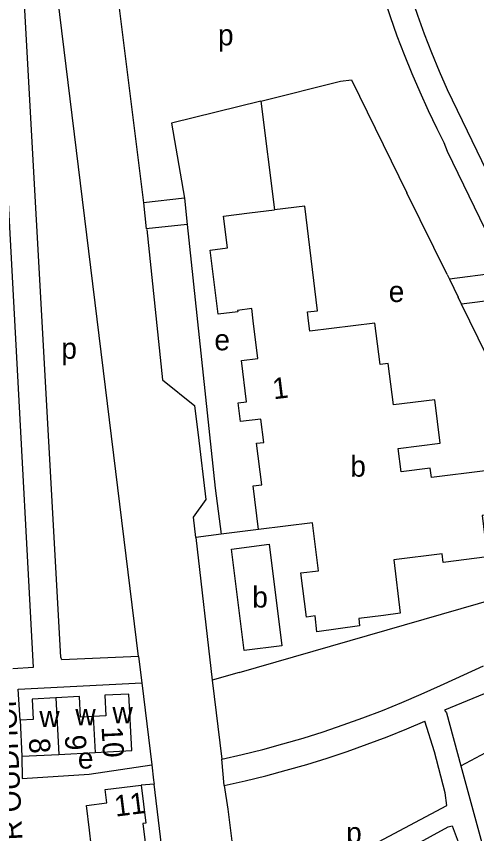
# Model space of a CAD drawing. Extents: x 157569 to 159501, y 382907 to 384670.
# Drawn here: x 158968.1 to 159055.8, y 383402.3 to 383558 of the extents above; entities that cross this region are included whole.
import ezdxf

# ---------------------------------------------------------------- set-up
doc = ezdxf.new("R2010")
doc.units = 0
for name, color, linetype in [('BLT_Basislijn', 7, 'Continuous'), ('BLT_Bebouwing', 7, 'Continuous'), ('BLT_Centroide', 7, 'Continuous'), ('BLT_Huisnummer', 7, 'Continuous'), ('BLT_Huisnummer_reeks', 7, 'Continuous'), ('BLT_Onderverdeling_panden', 7, 'Continuous'), ('BLT_Straatnaam_verkleind', 7, 'Continuous')]:
    doc.layers.add(name, color=color, linetype=linetype)

msp = doc.modelspace()

# ---------------------------------------------------------------- linework, layer by layer
at = {"layer": 'BLT_Basislijn'}
for p, q in [((158986.65, 383568.38), (158992.35, 383522.47)), ((158991.4, 383436.09), (158976.02, 383561.51)), ((159014.71, 383541.81), (158997.71, 383537.61)), ((159014.71, 383541.81), (159017.32, 383521.12)), ((158997.71, 383537.61), (159000.13, 383523.31)), ((159053.97, 383536.19), (159078.77, 383484.5)), ((159049.52, 383533.92), (159050.18, 383532.32)), ((159050.18, 383532.32), (159061.28, 383509.28)), ((159050.13, 383508.83), (159042.48, 383524.33)), ((159000.13, 383523.31), (158992.35, 383522.47)), ((158992.35, 383522.47), (158992.88, 383517.5)), ((159000.13, 383523.31), (159000.66, 383518.34)), ((159000.66, 383518.34), (158992.88, 383517.5)), ((159050.13, 383508.83), (159050.59, 383507.89)), ((159061.28, 383509.28), (159050.59, 383507.89)), ((159050.59, 383507.89), (159052.25, 383504.52)), ((159052.92, 383503.15), (159052.25, 383504.52)), ((159063.57, 383504.54), (159052.92, 383503.15)), ((159014.25, 383460.27), (159007.15, 383459.35)), ((159007.15, 383459.35), (159002.31, 383458.73)), ((159002.31, 383458.73), (159005.44, 383431.57)), ((158991.4, 383436.09), (158992.01, 383431.08)), ((159049.58, 383430.87), (159057.07, 383434.28)), ((159052.79, 383415.23), (159086.49, 383433.6)), ((159010.57, 383433.04), (159005.44, 383431.57)), ((158992.01, 383431.08), (158993.91, 383415.47)), ((159005.44, 383431.57), (159007.26, 383416.5)), ((159050.03, 383425.36), (159052.79, 383415.23)), ((159007.74, 383411.49), (159007.26, 383416.5)), ((158994.36, 383411.78), (158991.89, 383411.58))]:
    msp.add_line(p, q, dxfattribs=at)
for points in [[(159035.67, 383595.07), (159036.2, 383591.31), (159036.81, 383587.55), (159037.5, 383583.82), (159038.27, 383580.09), (159039.12, 383576.39), (159040.04, 383572.7), (159041.04, 383569.03), (159042.12, 383565.39), (159043.28, 383561.76), (159044.51, 383558.17), (159045.81, 383554.6), (159047.2, 383551.05), (159048.65, 383547.54), (159050.18, 383544.06), (159053.97, 383536.19)], [(159033.08, 383580.46), (159033.14, 383580.18), (159033.97, 383576.42), (159034.88, 383572.68), (159035.87, 383568.95), (159036.94, 383565.25), (159038.08, 383561.57), (159039.3, 383557.91), (159040.6, 383554.28), (159041.97, 383550.68), (159043.41, 383547.11), (159044.93, 383543.56), (159046.52, 383540.05), (159048.18, 383536.58), (159049.52, 383533.92)], [(158991.4, 383436.09), (158976.81, 383435.46), (158976.6, 383435.94), (158969.71, 383560.27)], [(158964.58, 383559.14), (158971.38, 383433.97), (158967.47, 383433.71)], [(159014.71, 383541.81), (159029.86, 383545.63), (159031.93, 383545.88), (159042.48, 383524.33)], [(159000.66, 383518.34), (159006.02, 383468.12)], [(158992.97, 383517.35), (158996, 383488.78), (159002.12, 383483.77)], [(159010.57, 383433.04), (159077.27, 383452.24), (159075.29, 383457.44), (159052.92, 383503.15)], [(159002.31, 383458.73), (159001.89, 383462.62), (159004.28, 383465.97), (159002.84, 383478.26), (159002.12, 383483.77)], [(159006.02, 383468.12), (159007.15, 383459.35)], [(158968.85, 383423.93), (158968.47, 383429.85), (158992.01, 383431.08)], [(159007.26, 383416.5), (159011.16, 383417.4), (159015.04, 383418.37), (159018.9, 383419.42), (159022.74, 383420.55), (159026.56, 383421.75), (159030.35, 383423.03), (159034.12, 383424.38), (159037.85, 383425.81), (159041.56, 383427.32), (159045.24, 383428.9), (159048.88, 383430.55), (159049.58, 383430.87)], [(159059.36, 383429.83), (159049.68, 383425.86), (159050.03, 383425.36)], [(159007.74, 383411.49), (159011.69, 383412.38), (159015.62, 383413.35), (159019.54, 383414.4), (159023.43, 383415.53), (159027.3, 383416.73), (159031.14, 383418.01), (159034.96, 383419.36), (159038.75, 383420.79), (159042.51, 383422.3), (159045.92, 383423.74)], [(159012.14, 383387.53), (159050.09, 383407.72), (159049.75, 383410.1), (159047.73, 383417.9), (159045.92, 383423.74)], [(158969.2, 383417.07), (158969.25, 383412.82), (158982.04, 383413.67), (158993.91, 383415.47)], [(158993.91, 383415.47), (158994.27, 383412.51), (158994.36, 383411.78)], [(159052.79, 383415.23), (159063.54, 383375.73), (159055.87, 383360.08), (159056.14, 383358.62), (159057.95, 383354.93)], [(158973.27, 383382.34), (158995.52, 383388.93), (158997.04, 383389.62), (158994.36, 383411.78)], [(159007.74, 383411.49), (159008.38, 383407.02), (159009.67, 383396.84), (159010.29, 383391.5), (159011.35, 383388.75), (159012.14, 383387.53)], [(159028.76, 383391.86), (159050.35, 383403.64), (159051.14, 383403.8), (159053, 383398.73), (159058.78, 383376.99), (159058.82, 383375.95), (159049, 383355.73)]]:
    msp.add_lwpolyline(points, dxfattribs=at)
at = {"layer": 'BLT_Bebouwing'}
for p, q in [((159023.06, 383521.82), (159017.32, 383521.12)), ((158969.2, 383417.07), (158976.22, 383417.43)), ((158976.22, 383417.43), (158983.13, 383417.79)), ((158992.23, 383404.25), (158992.74, 383400.13))]:
    msp.add_line(p, q, dxfattribs=at)
for points in [[(159007.58, 383519.92), (159012.53, 383520.53), (159017.32, 383521.12)], [(159048.85, 383476.68), (159047.83, 383484.94), (159039.92, 383483.97), (159038.94, 383491.89), (159037.39, 383491.7), (159036.42, 383499.56), (159024.02, 383498.03), (159023.76, 383500), (159023.55, 383501.68), (159025.5, 383501.92), (159023.06, 383521.82)], [(159014.25, 383460.27), (159013.23, 383468.56), (159014.86, 383468.76), (159013.89, 383476.67), (159015.27, 383476.84), (159014.72, 383481.28), (159010.81, 383480.79), (159010.37, 383484.34), (159011.99, 383484.54), (159011.01, 383492.45), (159014.14, 383492.83), (159013.25, 383500), (159012.96, 383502.31), (159010.27, 383501.98), (159010.31, 383501.69), (159006.55, 383501.23), (159005.05, 383513.46), (159008.32, 383513.86), (159007.58, 383519.92)], [(159057.37, 383471.41), (159047.15, 383470.15), (159046.93, 383471.93), (159041.38, 383471.24), (159040.83, 383475.7), (159048.85, 383476.68)], [(159057.37, 383471.41), (159058.39, 383463.14), (159056.82, 383462.94), (159057.79, 383455.03), (159049.43, 383454), (159049.23, 383455.64), (159039.99, 383454.5), (159041.24, 383444.3), (159038.05, 383443.9), (159033.33, 383443.31)], [(159033.33, 383443.31), (159033.5, 383441.93), (159025.38, 383440.8), (159025.01, 383443.8), (159023.36, 383443.56), (159022.32, 383451.99), (159025.67, 383452.4), (159024.54, 383461.54), (159014.25, 383460.27)], [(158983.13, 383417.79), (158990.13, 383418.15), (158989.57, 383428.93), (158985, 383428.69), (158985.2, 383424.78), (158982.78, 383424.66)], [(158975.66, 383428.2), (158971.17, 383427.97), (158971.38, 383424.06), (158968.85, 383423.93)], [(158982.78, 383424.66), (158980.35, 383424.53), (158980.15, 383428.43), (158975.66, 383428.2)], [(158968.85, 383423.93), (158969.2, 383417.07)], [(158982.08, 383402.99), (158981.49, 383407.72), (158985.36, 383408.2), (158985.05, 383410.73), (158991.89, 383411.58)], [(158991.89, 383411.58), (158992.79, 383404.32), (158992.23, 383404.25)], [(158978.59, 383398.39), (158981.24, 383398.72), (158981.4, 383397.41), (158984.1, 383397.75), (158983.77, 383400.41), (158982.42, 383400.24), (158982.08, 383402.99)]]:
    msp.add_lwpolyline(points, dxfattribs=at)
msp.add_lwpolyline([(159009.13, 383456.54), (159016.26, 383457.43), (159018.67, 383438.08), (159011.54, 383437.19)], close=True, dxfattribs=at)
at = {"layer": 'BLT_Onderverdeling_panden'}
for p, q in [((158975.66, 383428.2), (158976.22, 383417.43)), ((158982.78, 383424.66), (158983.13, 383417.79))]:
    msp.add_line(p, q, dxfattribs=at)

# ---------------------------------------------------------------- texts
at = {"layer": 'BLT_Centroide'}
for s, p in [('p', (159006.53, 383552.43)), ('e', (159039.03, 383503.57)), ('e', (159005.84, 383494.37)), ('p', (158976.71, 383492.75)), ('b', (159031.72, 383470.31)), ('b', (159013.06, 383445.39)), ('w', (158979.39, 383422.98)), ('w', (158986.45, 383423.36)), ('w', (158972.53, 383422.64)), ('e', (158979.86, 383414.73)), ('p', (159030.93, 383400.52))]:
    msp.add_text(s, height=4, dxfattribs=at).set_placement(p)
at = {"layer": 'BLT_Huisnummer'}
for s, rotation, p in [('1', 7.0278, (159017.14, 383485.03)), ('10', 272.947, (158984.37, 383422.66)), ('8', 272.947, (158970.53, 383420.47)), ('9', 272.947, (158977.38, 383421.07))]:
    msp.add_text(s, height=4, rotation=rotation, dxfattribs=at).set_placement(p)
at = {"layer": 'BLT_Huisnummer_reeks'}
msp.add_text('11', height=4, rotation=7.0937, dxfattribs=at).set_placement((158987.04, 383405.57))
at = {"layer": 'BLT_Straatnaam_verkleind'}
msp.add_text('PIETER OUDHOF', height=4, rotation=92.7263, dxfattribs=at).set_placement((158970.07, 383385.72))

doc.saveas('drawing.dxf')
